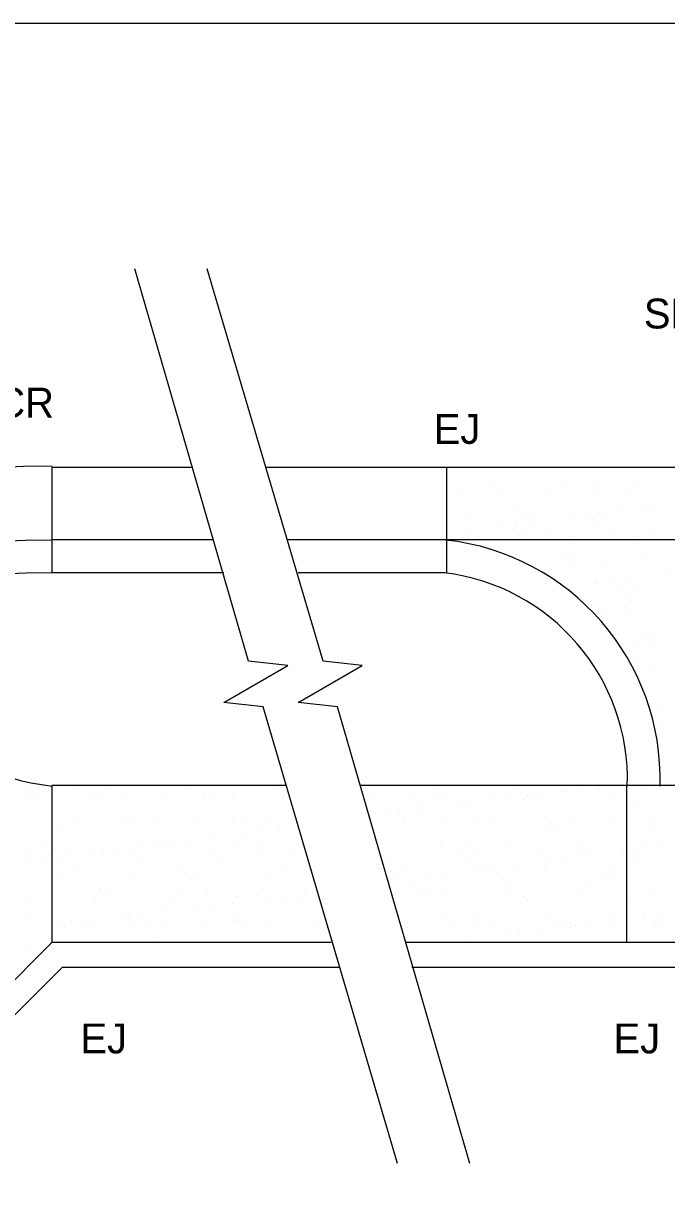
# Model space of a CAD drawing. Extents: x -118779 to -116979, y -104389 to -102939.
# Drawn here: x -118463.7 to -118334.6, y -103172.4 to -102939.3 of the extents above; entities that cross this region are included whole.
import ezdxf

# ---------------------------------------------------------------- set-up
doc = ezdxf.new("R2010")
doc.units = 0
doc.layers.add('Default', color=7, linetype='Continuous')
doc.layers.add('Misc CnstDet(22)', color=7, linetype='Continuous')

msp = doc.modelspace()

# ---------------------------------------------------------------- linework, layer by layer
at = {"layer": 'Default'}
msp.add_lwpolyline([(-118779.39, -102939.25), (-116979.39, -102939.25), (-116979.39, -104389.25), (-118779.39, -104389.25)], close=True, dxfattribs=at)
at = {"layer": 'Misc CnstDet(22)'}
for p, q in [((-118457.9, -103049.49), (-118457.9, -103028.34)), ((-118378.68, -103049.49), (-118378.68, -103028.34)), ((-118367.07, -103028.34), (-118367.07, -103028.34)), ((-118350.47, -103028.34), (-118350.47, -103028.34)), ((-118369.97, -103032.07), (-118369.97, -103032.07)), ((-118354.62, -103032.48), (-118354.62, -103032.48)), ((-118348.82, -103032.07), (-118348.82, -103032.07)), ((-118340.93, -103032.07), (-118340.93, -103032.07)), ((-118375.36, -103033.73), (-118375.36, -103033.73)), ((-118368.72, -103032.9), (-118368.72, -103032.9)), ((-118359.18, -103033.73), (-118359.18, -103033.73)), ((-118347.99, -103032.9), (-118347.99, -103032.9)), ((-118342.59, -103033.31), (-118342.59, -103033.31)), ((-118364.58, -103036.63), (-118364.58, -103036.63)), ((-118343.42, -103037.05), (-118343.42, -103037.05)), ((-118339.69, -103036.63), (-118339.69, -103036.63)), ((-118336.79, -103036.22), (-118336.79, -103036.22)), ((-118374.95, -103037.88), (-118374.95, -103037.88)), ((-118363.75, -103037.46), (-118363.75, -103037.46)), ((-118361.26, -103037.46), (-118361.26, -103037.46)), ((-118360.84, -103039.54), (-118360.84, -103039.54)), ((-118353.79, -103038.71), (-118353.79, -103038.71)), ((-118350.89, -103038.29), (-118350.89, -103038.29)), ((-118347.99, -103037.46), (-118347.99, -103037.46)), ((-118346.74, -103037.88), (-118346.74, -103037.88)), ((-118374.95, -103041.61), (-118374.95, -103041.61)), ((-118367.89, -103040.37), (-118367.89, -103040.37)), ((-118364.99, -103039.95), (-118364.99, -103039.95)), ((-118364.99, -103040.37), (-118364.99, -103040.37)), ((-118362.92, -103041.61), (-118362.92, -103041.61)), ((-118359.18, -103041.61), (-118359.18, -103041.61)), ((-118348.4, -103040.37), (-118348.4, -103040.37)), ((-118346.33, -103041.61), (-118346.33, -103041.61)), ((-118368.31, -103042.85), (-118368.31, -103042.85)), ((-118364.16, -103042.02), (-118364.16, -103042.02)), ((-118354.21, -103042.44), (-118354.21, -103042.44)), ((-118340.52, -103042.44), (-118340.52, -103042.44)), ((-118338.03, -103042.02), (-118338.03, -103042.02)), ((-118337.2, -103042.85), (-118337.2, -103042.85)), ((-118360.84, -103047.83), (-118360.84, -103047.83)), ((-118354.62, -103046.59), (-118354.62, -103046.59)), ((-118353.79, -103046.59), (-118353.79, -103046.59)), ((-118352.96, -103047.42), (-118352.96, -103047.42)), ((-118347.57, -103047.83), (-118347.57, -103047.83)), ((-118338.45, -103046.59), (-118338.45, -103046.59)), ((-118345.91, -103051.15), (-118345.91, -103051.15)), ((-118341.76, -103050.73), (-118341.76, -103050.73)), ((-118334.71, -103049.91), (-118334.71, -103049.91)), ((-118353.79, -103052.81), (-118353.79, -103052.81)), ((-118348.82, -103051.56), (-118348.82, -103051.56)), ((-118348.4, -103051.56), (-118348.4, -103051.56)), ((-118344.25, -103053.22), (-118344.25, -103053.22)), ((-118340.11, -103052.39), (-118340.11, -103052.39)), ((-118342.18, -103054.88), (-118342.18, -103054.88)), ((-118347.16, -103057.79), (-118347.16, -103057.79)), ((-118343.01, -103056.54), (-118343.01, -103056.54)), ((-118342.18, -103057.37), (-118342.18, -103057.37)), ((-118339.69, -103062.76), (-118339.69, -103062.76)), ((-118337.62, -103061.52), (-118337.62, -103061.52)), ((-118341.35, -103064.42), (-118341.35, -103064.42)), ((-118336.79, -103063.59), (-118336.79, -103063.59)), ((-118340.11, -103066.5), (-118340.11, -103066.5)), ((-118338.03, -103068.15), (-118338.03, -103068.15)), ((-118339.28, -103072.72), (-118339.28, -103072.72)), ((-118336.37, -103077.28), (-118336.37, -103077.28)), ((-118335.96, -103079.77), (-118335.96, -103079.77)), ((-118336.37, -103081.84), (-118336.37, -103081.84)), ((-118462.88, -103093.04), (-118462.88, -103093.04)), ((-118457.9, -103123.73), (-118457.9, -103092.21)), ((-118452.51, -103092.63), (-118452.51, -103092.63)), ((-118446.28, -103093.04), (-118446.28, -103093.04)), ((-118430.11, -103093.04), (-118430.11, -103093.04)), ((-118413.52, -103093.04), (-118413.52, -103093.04)), ((-118380.75, -103093.04), (-118380.75, -103093.04)), ((-118364.58, -103093.04), (-118364.58, -103093.04)), ((-118348.4, -103092.63), (-118348.4, -103092.63)), ((-118347.99, -103093.04), (-118347.99, -103093.04)), ((-118342.59, -103123.73), (-118342.59, -103092.21)), ((-118338.86, -103093.04), (-118338.86, -103093.04)), ((-118463.29, -103095.11), (-118463.29, -103095.11)), ((-118460.39, -103094.7), (-118460.39, -103094.7)), ((-118459.56, -103093.46), (-118459.56, -103093.46)), ((-118449.6, -103095.11), (-118449.6, -103095.11)), ((-118448.36, -103093.87), (-118448.36, -103093.87)), ((-118444.21, -103094.7), (-118444.21, -103094.7)), ((-118435.5, -103094.7), (-118435.5, -103094.7)), ((-118427.62, -103094.7), (-118427.62, -103094.7)), ((-118427.21, -103094.28), (-118427.21, -103094.28)), ((-118426.38, -103095.11), (-118426.38, -103095.11)), ((-118421.81, -103094.28), (-118421.81, -103094.28)), ((-118411.44, -103094.7), (-118411.44, -103094.7)), ((-118394.85, -103094.28), (-118394.85, -103094.28)), ((-118394.02, -103093.87), (-118394.02, -103093.87)), ((-118384.9, -103094.7), (-118384.9, -103094.7)), ((-118384.07, -103095.53), (-118384.07, -103095.53)), ((-118380.34, -103093.87), (-118380.34, -103093.87)), ((-118378.68, -103094.28), (-118378.68, -103094.28)), ((-118369.97, -103095.11), (-118369.97, -103095.11)), ((-118366.65, -103093.87), (-118366.65, -103093.87)), ((-118363.33, -103095.11), (-118363.33, -103095.11)), ((-118362.5, -103094.28), (-118362.5, -103094.28)), ((-118362.09, -103094.28), (-118362.09, -103094.28)), ((-118360.01, -103093.87), (-118360.01, -103093.87)), ((-118355.45, -103093.46), (-118355.45, -103093.46)), ((-118352.55, -103093.46), (-118352.55, -103093.46)), ((-118345.91, -103094.28), (-118345.91, -103094.28)), ((-118342.59, -103095.53), (-118342.59, -103095.53)), ((-118388.22, -103097.6), (-118388.22, -103097.6)), ((-118384.07, -103097.19), (-118384.07, -103097.19)), ((-118376.6, -103096.36), (-118376.6, -103096.36)), ((-118374.12, -103095.94), (-118374.12, -103095.94)), ((-118341.35, -103096.36), (-118341.35, -103096.36)), ((-118456.24, -103100.09), (-118456.24, -103100.09)), ((-118452.51, -103099.68), (-118452.51, -103099.68)), ((-118442.97, -103098.85), (-118442.97, -103098.85)), ((-118442.14, -103099.68), (-118442.14, -103099.68)), ((-118442.14, -103099.68), (-118442.14, -103099.68)), ((-118436.33, -103099.68), (-118436.33, -103099.68)), ((-118428.86, -103099.68), (-118428.86, -103099.68)), ((-118421.81, -103099.26), (-118421.81, -103099.26)), ((-118419.74, -103099.68), (-118419.74, -103099.68)), ((-118414.76, -103099.26), (-118414.76, -103099.26)), ((-118391.12, -103098.02), (-118391.12, -103098.02)), ((-118387.39, -103099.26), (-118387.39, -103099.26)), ((-118386.97, -103099.68), (-118386.97, -103099.68)), ((-118379.51, -103099.68), (-118379.51, -103099.68)), ((-118373.29, -103098.85), (-118373.29, -103098.85)), ((-118370.38, -103099.68), (-118370.38, -103099.68)), ((-118359.18, -103098.43), (-118359.18, -103098.43)), ((-118358.36, -103100.09), (-118358.36, -103100.09)), ((-118354.21, -103099.68), (-118354.21, -103099.68)), ((-118345.91, -103098.43), (-118345.91, -103098.43)), ((-118337.62, -103099.68), (-118337.62, -103099.68)), ((-118419.33, -103101.75), (-118419.33, -103101.75)), ((-118416.42, -103101.34), (-118416.42, -103101.34)), ((-118412.27, -103100.92), (-118412.27, -103100.92)), ((-118357.11, -103100.92), (-118357.11, -103100.92)), ((-118336.79, -103100.51), (-118336.79, -103100.51)), ((-118459.14, -103103.41), (-118459.14, -103103.41)), ((-118457.9, -103104.24), (-118457.9, -103104.24)), ((-118440.48, -103104.65), (-118440.48, -103104.65)), ((-118437.57, -103103.82), (-118437.57, -103103.82)), ((-118435.09, -103104.65), (-118435.09, -103104.65)), ((-118433.43, -103103.82), (-118433.43, -103103.82)), ((-118430.94, -103103.41), (-118430.94, -103103.41)), ((-118426.38, -103102.58), (-118426.38, -103102.58)), ((-118421.4, -103104.65), (-118421.4, -103104.65)), ((-118416.42, -103103.82), (-118416.42, -103103.82)), ((-118407.71, -103104.65), (-118407.71, -103104.65)), ((-118379.92, -103103.82), (-118379.92, -103103.82)), ((-118374.12, -103104.65), (-118374.12, -103104.65)), ((-118366.24, -103103.82), (-118366.24, -103103.82)), ((-118352.13, -103103.41), (-118352.13, -103103.41)), ((-118338.45, -103103.41), (-118338.45, -103103.41)), ((-118336.37, -103104.65), (-118336.37, -103104.65)), ((-118462.88, -103105.07), (-118462.88, -103105.07)), ((-118459.14, -103107.14), (-118459.14, -103107.14)), ((-118458.73, -103106.31), (-118458.73, -103106.31)), ((-118455, -103106.31), (-118455, -103106.31)), ((-118449.6, -103105.07), (-118449.6, -103105.07)), ((-118447.53, -103105.48), (-118447.53, -103105.48)), ((-118445.04, -103105.07), (-118445.04, -103105.07)), ((-118442.14, -103106.31), (-118442.14, -103106.31)), ((-118425.55, -103106.31), (-118425.55, -103106.31)), ((-118415.59, -103105.07), (-118415.59, -103105.07)), ((-118409.37, -103106.31), (-118409.37, -103106.31)), ((-118376.6, -103106.31), (-118376.6, -103106.31)), ((-118373.29, -103105.48), (-118373.29, -103105.48)), ((-118360.01, -103106.31), (-118360.01, -103106.31)), ((-118355.04, -103107.14), (-118355.04, -103107.14)), ((-118352.55, -103105.07), (-118352.55, -103105.07)), ((-118350.89, -103106.31), (-118350.89, -103106.31)), ((-118343.84, -103106.31), (-118343.84, -103106.31)), ((-118343.42, -103105.48), (-118343.42, -103105.48)), ((-118340.93, -103105.07), (-118340.93, -103105.07)), ((-118462.05, -103107.56), (-118462.05, -103107.56)), ((-118456.24, -103107.97), (-118456.24, -103107.97)), ((-118453.34, -103108.39), (-118453.34, -103108.39)), ((-118440.06, -103107.97), (-118440.06, -103107.97)), ((-118432.18, -103108.8), (-118432.18, -103108.8)), ((-118423.47, -103107.56), (-118423.47, -103107.56)), ((-118411.03, -103109.22), (-118411.03, -103109.22)), ((-118407.3, -103107.56), (-118407.3, -103107.56)), ((-118390.71, -103107.56), (-118390.71, -103107.56)), ((-118389.88, -103109.22), (-118389.88, -103109.22)), ((-118386.97, -103109.22), (-118386.97, -103109.22)), ((-118374.12, -103107.56), (-118374.12, -103107.56)), ((-118372.87, -103108.8), (-118372.87, -103108.8)), ((-118372.04, -103109.22), (-118372.04, -103109.22)), ((-118369.14, -103108.8), (-118369.14, -103108.8)), ((-118364.99, -103108.39), (-118364.99, -103108.39)), ((-118359.18, -103108.8), (-118359.18, -103108.8)), ((-118357.94, -103107.56), (-118357.94, -103107.56)), ((-118357.94, -103107.56), (-118357.94, -103107.56)), ((-118345.5, -103108.8), (-118345.5, -103108.8)), ((-118341.35, -103107.56), (-118341.35, -103107.56)), ((-118455.82, -103110.05), (-118455.82, -103110.05)), ((-118442.14, -103110.05), (-118442.14, -103110.05)), ((-118431.35, -103109.63), (-118431.35, -103109.63)), ((-118428.45, -103110.05), (-118428.45, -103110.05)), ((-118414.35, -103109.63), (-118414.35, -103109.63)), ((-118389.05, -103110.05), (-118389.05, -103110.05)), ((-118386.14, -103111.29), (-118386.14, -103111.29)), ((-118383.24, -103110.88), (-118383.24, -103110.88)), ((-118379.09, -103110.05), (-118379.09, -103110.05)), ((-118368.72, -103109.63), (-118368.72, -103109.63)), ((-118347.57, -103110.05), (-118347.57, -103110.05)), ((-118346.33, -103110.88), (-118346.33, -103110.88)), ((-118448.36, -103112.95), (-118448.36, -103112.95)), ((-118448.36, -103113.36), (-118448.36, -103113.36)), ((-118447.11, -103114.19), (-118447.11, -103114.19)), ((-118431.77, -103112.95), (-118431.77, -103112.95)), ((-118426.79, -103113.78), (-118426.79, -103113.78)), ((-118415.59, -103112.95), (-118415.59, -103112.95)), ((-118407.3, -103113.78), (-118407.3, -103113.78)), ((-118405.64, -103113.78), (-118405.64, -103113.78)), ((-118384.49, -103114.19), (-118384.49, -103114.19)), ((-118382.83, -103112.95), (-118382.83, -103112.95)), ((-118379.51, -103114.19), (-118379.51, -103114.19)), ((-118366.24, -103112.53), (-118366.24, -103112.53)), ((-118366.24, -103114.19), (-118366.24, -103114.19)), ((-118351.72, -103113.78), (-118351.72, -103113.78)), ((-118350.06, -103112.53), (-118350.06, -103112.53)), ((-118338.03, -103113.36), (-118338.03, -103113.36)), ((-118462.46, -103115.44), (-118462.46, -103115.44)), ((-118449.19, -103115.44), (-118449.19, -103115.44)), ((-118434.67, -103115.02), (-118434.67, -103115.02)), ((-118425.96, -103116.27), (-118425.96, -103116.27)), ((-118421.81, -103115.85), (-118421.81, -103115.85)), ((-118420.98, -103114.61), (-118420.98, -103114.61)), ((-118414.35, -103115.02), (-118414.35, -103115.02)), ((-118411.86, -103114.61), (-118411.86, -103114.61)), ((-118407.71, -103114.61), (-118407.71, -103114.61)), ((-118404.81, -103114.61), (-118404.81, -103114.61)), ((-118363.33, -103114.61), (-118363.33, -103114.61)), ((-118362.5, -103115.44), (-118362.5, -103115.44)), ((-118341.76, -103115.02), (-118341.76, -103115.02)), ((-118462.88, -103118.76), (-118462.88, -103118.76)), ((-118442.97, -103118.76), (-118442.97, -103118.76)), ((-118442.55, -103118.34), (-118442.55, -103118.34)), ((-118440.06, -103118.34), (-118440.06, -103118.34)), ((-118435.92, -103117.51), (-118435.92, -103117.51)), ((-118428.45, -103116.68), (-118428.45, -103116.68)), ((-118421.4, -103118.34), (-118421.4, -103118.34)), ((-118358.77, -103118.76), (-118358.77, -103118.76)), ((-118345.08, -103118.76), (-118345.08, -103118.76)), ((-118338.86, -103118.34), (-118338.86, -103118.34)), ((-118335.96, -103117.93), (-118335.96, -103117.93)), ((-118457.07, -103120.41), (-118457.07, -103120.41)), ((-118455.41, -103120.41), (-118455.41, -103120.41)), ((-118454.17, -103119.59), (-118454.17, -103119.59)), ((-118454.17, -103120), (-118454.17, -103120)), ((-118452.09, -103120.83), (-118452.09, -103120.83)), ((-118450.02, -103119.59), (-118450.02, -103119.59)), ((-118441.72, -103120), (-118441.72, -103120)), ((-118437.99, -103119.59), (-118437.99, -103119.59)), ((-118435.5, -103120.83), (-118435.5, -103120.83)), ((-118428.04, -103120), (-118428.04, -103120)), ((-118421.4, -103119.59), (-118421.4, -103119.59)), ((-118420.57, -103119.59), (-118420.57, -103119.59)), ((-118419.33, -103120.83), (-118419.33, -103120.83)), ((-118413.93, -103119.59), (-118413.93, -103119.59)), ((-118405.22, -103119.59), (-118405.22, -103119.59)), ((-118402.73, -103120.83), (-118402.73, -103120.83)), ((-118386.56, -103119.59), (-118386.56, -103119.59)), ((-118386.56, -103120.83), (-118386.56, -103120.83)), ((-118379.09, -103119.17), (-118379.09, -103119.17)), ((-118378.26, -103120), (-118378.26, -103120)), ((-118372.46, -103119.17), (-118372.46, -103119.17)), ((-118372.46, -103119.59), (-118372.46, -103119.59)), ((-118369.97, -103120.83), (-118369.97, -103120.83)), ((-118357.53, -103119.59), (-118357.53, -103119.59)), ((-118355.87, -103119.59), (-118355.87, -103119.59)), ((-118353.79, -103120.83), (-118353.79, -103120.83)), ((-118352.96, -103120.41), (-118352.96, -103120.41)), ((-118350.06, -103120), (-118350.06, -103120)), ((-118345.91, -103119.59), (-118345.91, -103119.59)), ((-118339.28, -103119.17), (-118339.28, -103119.17)), ((-118337.2, -103120.83), (-118337.2, -103120.83)), ((-118336.79, -103120), (-118336.79, -103120)), ((-118335.54, -103120.83), (-118335.54, -103120.83)), ((-118458.31, -103122.9), (-118458.31, -103122.9)), ((-118437.57, -103123.32), (-118437.57, -103123.32)), ((-118374.12, -103123.32), (-118374.12, -103123.32)), ((-118367.07, -103122.07), (-118367.07, -103122.07)), ((-118364.16, -103121.66), (-118364.16, -103121.66)), ((-118360.01, -103121.24), (-118360.01, -103121.24)), ((-118586.48, -103251.89), (-118457.9, -103123.73)), ((-118462.05, -103125.39), (-118462.05, -103125.39)), ((-118416.01, -103123.73), (-118416.01, -103123.73)), ((-118337.62, -103123.73), (-118337.62, -103123.73)), ((-118460.39, -103126.22), (-118460.39, -103126.22))]:
    msp.add_line(p, q, dxfattribs=at)
for points in [[(-118388.63, -103168.11), (-118415.59, -103076.45), (-118423.47, -103075.62), (-118410.62, -103068.15), (-118418.5, -103067.33), (-118441.31, -102988.52)], [(-118374.12, -103168.11), (-118400.66, -103076.45), (-118408.54, -103075.62), (-118395.68, -103068.15), (-118403.56, -103067.33), (-118426.79, -102988.52)], [(-118457.9, -103028.34), (-118429.69, -103028.34)], [(-118415.18, -103028.34), (-118094.15, -103028.34)], [(-118457.9, -103042.85), (-118425.55, -103042.85)], [(-118410.62, -103042.85), (-118094.15, -103042.85)], [(-118457.9, -103049.49), (-118423.47, -103049.49)], [(-118408.54, -103049.49), (-118379.09, -103049.49)], [(-118457.9, -103092.21), (-118411.03, -103092.21)], [(-118396.1, -103092.21), (-118094.15, -103092.21)], [(-118457.9, -103123.73), (-118401.91, -103123.73)], [(-118386.97, -103123.73), (-118094.15, -103123.73)], [(-118581.5, -103791.92), (-118581.5, -103253.97), (-118455.82, -103128.71), (-118400.25, -103128.71)], [(-118385.73, -103128.71), (-118094.15, -103128.71)]]:
    msp.add_lwpolyline(points, dxfattribs=at)
for centre, radius, start, end in [((-118457.89, -103252.04), 223.87, 90, 180), ((-118457.89, -103252.04), 209.05, 90, 180), ((-118384.17, -103090.99), 48.29, 358.3614, 83.7059), ((-118452.6, -103044.37), 48.29, 183.6428, 263.7059), ((-118457.89, -103252.04), 202.47, 90, 180), ((-118384.17, -103090.99), 41.71, 358.1026, 83.2268)]:
    msp.add_arc(centre, radius, start, end, dxfattribs=at)

# ---------------------------------------------------------------- texts
for s, p in [('SEE STD PLAN FOR DRIVEWAYS', (-118339.16, -103000.52)), ('EJ AT ECR', (-118498.57, -103018.4)), ('EJ', (-118381.34, -103023.68)), ('EJ', (-118452.26, -103146.03)), ('EJ', (-118345.25, -103146.03))]:
    msp.add_text(s, height=6, dxfattribs=at).set_placement(p)

doc.saveas('drawing.dxf')
